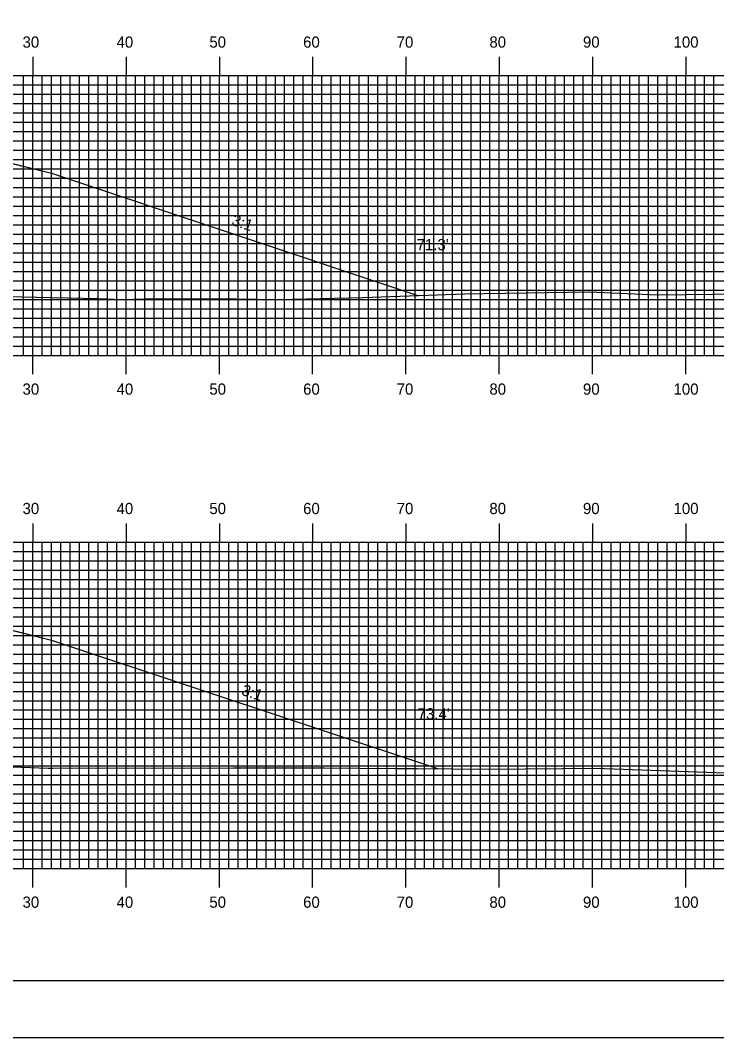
# Model space of a CAD drawing. Extents: x 1787369 to 1787713, y 442591 to 442811.
# Drawn here: x 1787563.8 to 1787638.4, y 442590.5 to 442699.6 of the extents above; entities that cross this region are included whole.
import ezdxf

# ---------------------------------------------------------------- set-up
doc = ezdxf.new("R2010")
doc.units = 0
for name, color, linetype in [('ANNOTATION', 7, 'Continuous'), ('BORDER', 7, 'Continuous'), ('D_Roadway_Centerline', 7, 'Continuous'), ('D_Roadway_SlopeLines', 7, 'Continuous'), ('D_Text_Standard', 7, 'Continuous'), ('H_V ANNOTATION', 7, 'Continuous'), ('MAJOR', 7, 'Continuous'), ('MINOR', 7, 'Continuous'), ('PLOT BOUNDARY', 7, 'Continuous'), ('S_Roadway_Centerline', 7, 'Continuous')]:
    doc.layers.add(name, color=color, linetype=linetype)

msp = doc.modelspace()

# ---------------------------------------------------------------- linework, layer by layer
at = {"layer": 'BORDER'}
msp.add_lwpolyline([(1787385.5, 442596.67), (1787705.5, 442596.67), (1787705.5, 442806.67), (1787385.5, 442806.67)], close=True, dxfattribs=at)
at = {"layer": 'D_Roadway_Centerline'}
for points in [[(1787471.54, 442672.25), (1787502.75, 442682.65), (1787506.42, 442683.57), (1787514.75, 442685.65), (1787523.1, 442685.99), (1787535.1, 442686.25), (1787547.1, 442686.52), (1787555.1, 442686.2), (1787563.47, 442684.11), (1787567.1, 442683.2), (1787606.38, 442670.11)], [(1787462.81, 442621.41), (1787495.6, 442632.35), (1787499.89, 442633.42), (1787507.6, 442635.35), (1787523.1, 442635.97), (1787535.1, 442636.23), (1787547.1, 442636.49), (1787555.1, 442636.17), (1787563.47, 442634.08), (1787567.1, 442633.17), (1787608.47, 442619.39)]]:
    msp.add_lwpolyline(points, dxfattribs=at)
at = {"layer": 'D_Roadway_SlopeLines'}
for points in [[(1787555.1, 442686.2), (1787567.1, 442683.2), (1787606.38, 442670.11)], [(1787555.1, 442636.17), (1787567.1, 442633.17), (1787608.47, 442619.39)]]:
    msp.add_lwpolyline(points, dxfattribs=at)
at = {"layer": 'MAJOR'}
for p, q in [((1787565.1, 442695.67), (1787565.1, 442693.67)), ((1787575.1, 442695.67), (1787575.1, 442693.67)), ((1787585.1, 442695.67), (1787585.1, 442693.67)), ((1787595.1, 442695.67), (1787595.1, 442693.67)), ((1787605.1, 442695.67), (1787605.1, 442693.67)), ((1787615.1, 442695.67), (1787615.1, 442693.67)), ((1787625.1, 442695.67), (1787625.1, 442693.67)), ((1787635.1, 442695.67), (1787635.1, 442693.67)), ((1787395.1, 442693.67), (1787675.1, 442693.67)), ((1787395.1, 442693.67), (1787675.1, 442693.67)), ((1787565.1, 442663.67), (1787565.1, 442693.67)), ((1787575.1, 442663.67), (1787575.1, 442693.67)), ((1787585.1, 442663.67), (1787585.1, 442693.67)), ((1787595.1, 442663.67), (1787595.1, 442693.67)), ((1787605.1, 442663.67), (1787605.1, 442693.67)), ((1787615.1, 442663.67), (1787615.1, 442693.67)), ((1787625.1, 442663.67), (1787625.1, 442693.67)), ((1787635.1, 442663.67), (1787635.1, 442693.67)), ((1787395.1, 442688.67), (1787675.1, 442688.67)), ((1787395.1, 442683.67), (1787675.1, 442683.67)), ((1787395.1, 442678.67), (1787675.1, 442678.67)), ((1787395.1, 442673.67), (1787675.1, 442673.67)), ((1787395.1, 442668.67), (1787675.1, 442668.67)), ((1787395.1, 442663.67), (1787675.1, 442663.67)), ((1787395.1, 442663.67), (1787675.1, 442663.67)), ((1787565.1, 442661.66), (1787565.1, 442663.67)), ((1787575.1, 442661.66), (1787575.1, 442663.67)), ((1787585.1, 442661.66), (1787585.1, 442663.67)), ((1787595.1, 442661.66), (1787595.1, 442663.67)), ((1787605.1, 442661.66), (1787605.1, 442663.67)), ((1787615.1, 442661.66), (1787615.1, 442663.67)), ((1787625.1, 442661.66), (1787625.1, 442663.67)), ((1787635.1, 442661.66), (1787635.1, 442663.67)), ((1787565.1, 442645.67), (1787565.1, 442643.67)), ((1787575.1, 442645.67), (1787575.1, 442643.67)), ((1787585.1, 442645.67), (1787585.1, 442643.67)), ((1787595.1, 442645.67), (1787595.1, 442643.67)), ((1787605.1, 442645.67), (1787605.1, 442643.67)), ((1787615.1, 442645.67), (1787615.1, 442643.67)), ((1787625.1, 442645.67), (1787625.1, 442643.67)), ((1787635.1, 442645.67), (1787635.1, 442643.67)), ((1787395.1, 442643.67), (1787675.1, 442643.67)), ((1787395.1, 442643.67), (1787675.1, 442643.67)), ((1787565.1, 442608.67), (1787565.1, 442643.67)), ((1787575.1, 442608.67), (1787575.1, 442643.67)), ((1787585.1, 442608.67), (1787585.1, 442643.67)), ((1787595.1, 442608.67), (1787595.1, 442643.67)), ((1787605.1, 442608.67), (1787605.1, 442643.67)), ((1787615.1, 442608.67), (1787615.1, 442643.67)), ((1787625.1, 442608.67), (1787625.1, 442643.67)), ((1787635.1, 442608.67), (1787635.1, 442643.67)), ((1787395.1, 442638.67), (1787675.1, 442638.67)), ((1787395.1, 442633.67), (1787675.1, 442633.67)), ((1787395.1, 442628.67), (1787675.1, 442628.67)), ((1787395.1, 442623.67), (1787675.1, 442623.67)), ((1787395.1, 442618.67), (1787675.1, 442618.67)), ((1787395.1, 442613.67), (1787675.1, 442613.67)), ((1787395.1, 442608.67), (1787675.1, 442608.67)), ((1787395.1, 442608.67), (1787675.1, 442608.67)), ((1787565.1, 442606.66), (1787565.1, 442608.67)), ((1787575.1, 442606.66), (1787575.1, 442608.67)), ((1787585.1, 442606.66), (1787585.1, 442608.67)), ((1787595.1, 442606.66), (1787595.1, 442608.67)), ((1787605.1, 442606.66), (1787605.1, 442608.67)), ((1787615.1, 442606.66), (1787615.1, 442608.67)), ((1787625.1, 442606.66), (1787625.1, 442608.67)), ((1787635.1, 442606.66), (1787635.1, 442608.67))]:
    msp.add_line(p, q, dxfattribs=at)
at = {"layer": 'MINOR'}
for p, q in [((1787564.1, 442663.67), (1787564.1, 442693.67)), ((1787566.1, 442663.67), (1787566.1, 442693.67)), ((1787567.1, 442663.67), (1787567.1, 442693.67)), ((1787568.1, 442663.67), (1787568.1, 442693.67)), ((1787569.1, 442663.67), (1787569.1, 442693.67)), ((1787570.1, 442663.67), (1787570.1, 442693.67)), ((1787571.1, 442663.67), (1787571.1, 442693.67)), ((1787572.1, 442663.67), (1787572.1, 442693.67)), ((1787573.1, 442663.67), (1787573.1, 442693.67)), ((1787574.1, 442663.67), (1787574.1, 442693.67)), ((1787576.1, 442663.67), (1787576.1, 442693.67)), ((1787577.1, 442663.67), (1787577.1, 442693.67)), ((1787578.1, 442663.67), (1787578.1, 442693.67)), ((1787579.1, 442663.67), (1787579.1, 442693.67)), ((1787580.1, 442663.67), (1787580.1, 442693.67)), ((1787581.1, 442663.67), (1787581.1, 442693.67)), ((1787582.1, 442663.67), (1787582.1, 442693.67)), ((1787583.1, 442663.67), (1787583.1, 442693.67)), ((1787584.1, 442663.67), (1787584.1, 442693.67)), ((1787586.1, 442663.67), (1787586.1, 442693.67)), ((1787587.1, 442663.67), (1787587.1, 442693.67)), ((1787588.1, 442663.67), (1787588.1, 442693.67)), ((1787589.1, 442663.67), (1787589.1, 442693.67)), ((1787590.1, 442663.67), (1787590.1, 442693.67)), ((1787591.1, 442663.67), (1787591.1, 442693.67)), ((1787592.1, 442663.67), (1787592.1, 442693.67)), ((1787593.1, 442663.67), (1787593.1, 442693.67)), ((1787594.1, 442663.67), (1787594.1, 442693.67)), ((1787596.1, 442663.67), (1787596.1, 442693.67)), ((1787597.1, 442663.67), (1787597.1, 442693.67)), ((1787598.1, 442663.67), (1787598.1, 442693.67)), ((1787599.1, 442663.67), (1787599.1, 442693.67)), ((1787600.1, 442663.67), (1787600.1, 442693.67)), ((1787601.1, 442663.67), (1787601.1, 442693.67)), ((1787602.1, 442663.67), (1787602.1, 442693.67)), ((1787603.1, 442663.67), (1787603.1, 442693.67)), ((1787604.1, 442663.67), (1787604.1, 442693.67)), ((1787606.1, 442663.67), (1787606.1, 442693.67)), ((1787607.1, 442663.67), (1787607.1, 442693.67)), ((1787608.1, 442663.67), (1787608.1, 442693.67)), ((1787609.1, 442663.67), (1787609.1, 442693.67)), ((1787610.1, 442663.67), (1787610.1, 442693.67)), ((1787611.1, 442663.67), (1787611.1, 442693.67)), ((1787612.1, 442663.67), (1787612.1, 442693.67)), ((1787613.1, 442663.67), (1787613.1, 442693.67)), ((1787614.1, 442663.67), (1787614.1, 442693.67)), ((1787616.1, 442663.67), (1787616.1, 442693.67)), ((1787617.1, 442663.67), (1787617.1, 442693.67)), ((1787618.1, 442663.67), (1787618.1, 442693.67)), ((1787619.1, 442663.67), (1787619.1, 442693.67)), ((1787620.1, 442663.67), (1787620.1, 442693.67)), ((1787621.1, 442663.67), (1787621.1, 442693.67)), ((1787622.1, 442663.67), (1787622.1, 442693.67)), ((1787623.1, 442663.67), (1787623.1, 442693.67)), ((1787624.1, 442663.67), (1787624.1, 442693.67)), ((1787626.1, 442663.67), (1787626.1, 442693.67)), ((1787627.1, 442663.67), (1787627.1, 442693.67)), ((1787628.1, 442663.67), (1787628.1, 442693.67)), ((1787629.1, 442663.67), (1787629.1, 442693.67)), ((1787630.1, 442663.67), (1787630.1, 442693.67)), ((1787631.1, 442663.67), (1787631.1, 442693.67)), ((1787632.1, 442663.67), (1787632.1, 442693.67)), ((1787633.1, 442663.67), (1787633.1, 442693.67)), ((1787634.1, 442663.67), (1787634.1, 442693.67)), ((1787636.1, 442663.67), (1787636.1, 442693.67)), ((1787637.1, 442663.67), (1787637.1, 442693.67)), ((1787638.1, 442663.67), (1787638.1, 442693.67)), ((1787395.1, 442692.67), (1787675.1, 442692.67)), ((1787395.1, 442691.67), (1787675.1, 442691.67)), ((1787395.1, 442690.67), (1787675.1, 442690.67)), ((1787395.1, 442689.67), (1787675.1, 442689.67)), ((1787395.1, 442687.67), (1787675.1, 442687.67)), ((1787395.1, 442686.67), (1787675.1, 442686.67)), ((1787395.1, 442685.67), (1787675.1, 442685.67)), ((1787395.1, 442684.67), (1787675.1, 442684.67)), ((1787395.1, 442682.67), (1787675.1, 442682.67)), ((1787395.1, 442681.67), (1787675.1, 442681.67)), ((1787395.1, 442680.67), (1787675.1, 442680.67)), ((1787395.1, 442679.67), (1787675.1, 442679.67)), ((1787395.1, 442677.67), (1787675.1, 442677.67)), ((1787395.1, 442676.67), (1787675.1, 442676.67)), ((1787395.1, 442675.67), (1787675.1, 442675.67)), ((1787395.1, 442674.67), (1787675.1, 442674.67)), ((1787395.1, 442672.67), (1787675.1, 442672.67)), ((1787395.1, 442671.67), (1787675.1, 442671.67)), ((1787395.1, 442670.67), (1787675.1, 442670.67)), ((1787395.1, 442669.67), (1787675.1, 442669.67)), ((1787395.1, 442667.67), (1787675.1, 442667.67)), ((1787395.1, 442666.67), (1787675.1, 442666.67)), ((1787395.1, 442665.67), (1787675.1, 442665.67)), ((1787395.1, 442664.67), (1787675.1, 442664.67)), ((1787564.1, 442608.67), (1787564.1, 442643.67)), ((1787566.1, 442608.67), (1787566.1, 442643.67)), ((1787567.1, 442608.67), (1787567.1, 442643.67)), ((1787568.1, 442608.67), (1787568.1, 442643.67)), ((1787569.1, 442608.67), (1787569.1, 442643.67)), ((1787570.1, 442608.67), (1787570.1, 442643.67)), ((1787571.1, 442608.67), (1787571.1, 442643.67)), ((1787572.1, 442608.67), (1787572.1, 442643.67)), ((1787573.1, 442608.67), (1787573.1, 442643.67)), ((1787574.1, 442608.67), (1787574.1, 442643.67)), ((1787576.1, 442608.67), (1787576.1, 442643.67)), ((1787577.1, 442608.67), (1787577.1, 442643.67)), ((1787578.1, 442608.67), (1787578.1, 442643.67)), ((1787579.1, 442608.67), (1787579.1, 442643.67)), ((1787580.1, 442608.67), (1787580.1, 442643.67)), ((1787581.1, 442608.67), (1787581.1, 442643.67)), ((1787582.1, 442608.67), (1787582.1, 442643.67)), ((1787583.1, 442608.67), (1787583.1, 442643.67)), ((1787584.1, 442608.67), (1787584.1, 442643.67)), ((1787586.1, 442608.67), (1787586.1, 442643.67)), ((1787587.1, 442608.67), (1787587.1, 442643.67)), ((1787588.1, 442608.67), (1787588.1, 442643.67)), ((1787589.1, 442608.67), (1787589.1, 442643.67)), ((1787590.1, 442608.67), (1787590.1, 442643.67)), ((1787591.1, 442608.67), (1787591.1, 442643.67)), ((1787592.1, 442608.67), (1787592.1, 442643.67)), ((1787593.1, 442608.67), (1787593.1, 442643.67)), ((1787594.1, 442608.67), (1787594.1, 442643.67)), ((1787596.1, 442608.67), (1787596.1, 442643.67)), ((1787597.1, 442608.67), (1787597.1, 442643.67)), ((1787598.1, 442608.67), (1787598.1, 442643.67)), ((1787599.1, 442608.67), (1787599.1, 442643.67)), ((1787600.1, 442608.67), (1787600.1, 442643.67)), ((1787601.1, 442608.67), (1787601.1, 442643.67)), ((1787602.1, 442608.67), (1787602.1, 442643.67)), ((1787603.1, 442608.67), (1787603.1, 442643.67)), ((1787604.1, 442608.67), (1787604.1, 442643.67)), ((1787606.1, 442608.67), (1787606.1, 442643.67)), ((1787607.1, 442608.67), (1787607.1, 442643.67)), ((1787608.1, 442608.67), (1787608.1, 442643.67)), ((1787609.1, 442608.67), (1787609.1, 442643.67)), ((1787610.1, 442608.67), (1787610.1, 442643.67)), ((1787611.1, 442608.67), (1787611.1, 442643.67)), ((1787612.1, 442608.67), (1787612.1, 442643.67)), ((1787613.1, 442608.67), (1787613.1, 442643.67)), ((1787614.1, 442608.67), (1787614.1, 442643.67)), ((1787616.1, 442608.67), (1787616.1, 442643.67)), ((1787617.1, 442608.67), (1787617.1, 442643.67)), ((1787618.1, 442608.67), (1787618.1, 442643.67)), ((1787619.1, 442608.67), (1787619.1, 442643.67)), ((1787620.1, 442608.67), (1787620.1, 442643.67)), ((1787621.1, 442608.67), (1787621.1, 442643.67)), ((1787622.1, 442608.67), (1787622.1, 442643.67)), ((1787623.1, 442608.67), (1787623.1, 442643.67)), ((1787624.1, 442608.67), (1787624.1, 442643.67)), ((1787626.1, 442608.67), (1787626.1, 442643.67)), ((1787627.1, 442608.67), (1787627.1, 442643.67)), ((1787628.1, 442608.67), (1787628.1, 442643.67)), ((1787629.1, 442608.67), (1787629.1, 442643.67)), ((1787630.1, 442608.67), (1787630.1, 442643.67)), ((1787631.1, 442608.67), (1787631.1, 442643.67)), ((1787632.1, 442608.67), (1787632.1, 442643.67)), ((1787633.1, 442608.67), (1787633.1, 442643.67)), ((1787634.1, 442608.67), (1787634.1, 442643.67)), ((1787636.1, 442608.67), (1787636.1, 442643.67)), ((1787637.1, 442608.67), (1787637.1, 442643.67)), ((1787638.1, 442608.67), (1787638.1, 442643.67)), ((1787395.1, 442642.67), (1787675.1, 442642.67)), ((1787395.1, 442641.67), (1787675.1, 442641.67)), ((1787395.1, 442640.67), (1787675.1, 442640.67)), ((1787395.1, 442639.67), (1787675.1, 442639.67)), ((1787395.1, 442637.67), (1787675.1, 442637.67)), ((1787395.1, 442636.67), (1787675.1, 442636.67)), ((1787395.1, 442635.67), (1787675.1, 442635.67)), ((1787395.1, 442634.67), (1787675.1, 442634.67)), ((1787395.1, 442632.67), (1787675.1, 442632.67)), ((1787395.1, 442631.67), (1787675.1, 442631.67)), ((1787395.1, 442630.67), (1787675.1, 442630.67)), ((1787395.1, 442629.67), (1787675.1, 442629.67)), ((1787395.1, 442627.67), (1787675.1, 442627.67)), ((1787395.1, 442626.67), (1787675.1, 442626.67)), ((1787395.1, 442625.67), (1787675.1, 442625.67)), ((1787395.1, 442624.67), (1787675.1, 442624.67)), ((1787395.1, 442622.67), (1787675.1, 442622.67)), ((1787395.1, 442621.67), (1787675.1, 442621.67)), ((1787395.1, 442620.67), (1787675.1, 442620.67)), ((1787395.1, 442619.67), (1787675.1, 442619.67)), ((1787395.1, 442617.67), (1787675.1, 442617.67)), ((1787395.1, 442616.67), (1787675.1, 442616.67)), ((1787395.1, 442615.67), (1787675.1, 442615.67)), ((1787395.1, 442614.67), (1787675.1, 442614.67)), ((1787395.1, 442612.67), (1787675.1, 442612.67)), ((1787395.1, 442611.67), (1787675.1, 442611.67)), ((1787395.1, 442610.67), (1787675.1, 442610.67)), ((1787395.1, 442609.67), (1787675.1, 442609.67))]:
    msp.add_line(p, q, dxfattribs=at)
at = {"layer": 'PLOT BOUNDARY'}
msp.add_lwpolyline([(1787369.32, 442590.55), (1787709.32, 442590.55), (1787709.32, 442810.55), (1787369.32, 442810.55)], close=True, dxfattribs=at)
at = {"layer": 'S_Roadway_Centerline'}
for points in [[(1787555.6, 442670.14), (1787572.15, 442669.78), (1787574.69, 442669.66), (1787578.43, 442669.77), (1787586.95, 442669.73), (1787591.41, 442669.67), (1787600.47, 442669.89), (1787611.42, 442670.29), (1787613.49, 442670.32), (1787624.76, 442670.49), (1787632.06, 442670.17), (1787643.85, 442670.32), (1787650.95, 442670.41), (1787659.55, 442670.25), (1787670.91, 442670.62), (1787671.69, 442670.65), (1787672.81, 442670.64), (1787675.1, 442670.68)], [(1787555.27, 442619.85), (1787566.74, 442619.43), (1787567.22, 442619.42), (1787586.59, 442619.47), (1787596.37, 442619.46), (1787603.97, 442619.39), (1787606.29, 442619.41), (1787613.92, 442619.31), (1787625.86, 442619.42), (1787626.43, 442619.41), (1787646.29, 442618.7), (1787649.11, 442618.62), (1787651.45, 442618.57), (1787655.15, 442618.43), (1787664.84, 442618.16), (1787668.25, 442618.14), (1787670.33, 442618.09), (1787671.24, 442618.11), (1787675.1, 442618.22)]]:
    msp.add_lwpolyline(points, dxfattribs=at)

# ---------------------------------------------------------------- texts
at = {"layer": 'ANNOTATION'}
for p in [(1787586.34, 442677.69), (1787587.39, 442627.32)]:
    msp.add_text('3:1', height=1.2, rotation=341.5652, dxfattribs=at).set_placement(p)
at = {"layer": 'D_Text_Standard'}
for s, p in [("71.3'", (1787606.25, 442674.96)), ("73.4'", (1787606.36, 442624.66))]:
    msp.add_text(s, height=1.2, dxfattribs=at).set_placement(p)
at = {"layer": 'H_V ANNOTATION'}
for s, p in [('30', (1787564, 442696.67)), ('40', (1787574.08, 442696.67)), ('50', (1787584.03, 442696.67)), ('60', (1787594.08, 442696.67)), ('70', (1787604.11, 442696.67)), ('80', (1787614.05, 442696.67)), ('90', (1787624.08, 442696.67)), ('100', (1787633.79, 442696.67)), ('30', (1787564, 442659.47)), ('40', (1787574.08, 442659.47)), ('50', (1787584.03, 442659.47)), ('60', (1787594.08, 442659.47)), ('70', (1787604.11, 442659.47)), ('80', (1787614.05, 442659.47)), ('90', (1787624.08, 442659.47)), ('100', (1787633.79, 442659.47)), ('30', (1787564, 442646.67)), ('40', (1787574.08, 442646.67)), ('50', (1787584.03, 442646.67)), ('60', (1787594.08, 442646.67)), ('70', (1787604.11, 442646.67)), ('80', (1787614.05, 442646.67)), ('90', (1787624.08, 442646.67)), ('100', (1787633.79, 442646.67)), ('30', (1787564, 442604.47)), ('40', (1787574.08, 442604.47)), ('50', (1787584.03, 442604.47)), ('60', (1787594.08, 442604.47)), ('70', (1787604.11, 442604.47)), ('80', (1787614.05, 442604.47)), ('90', (1787624.08, 442604.47)), ('100', (1787633.79, 442604.47))]:
    msp.add_text(s, height=1.2, dxfattribs=at).set_placement(p)

doc.saveas('drawing.dxf')
